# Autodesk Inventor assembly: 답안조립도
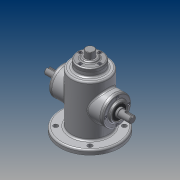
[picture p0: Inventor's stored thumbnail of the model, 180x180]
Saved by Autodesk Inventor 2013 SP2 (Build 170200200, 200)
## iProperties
Created: 2014-12
Part Number: 답안조립도
Document SubType Name: Assembly
Designer: user
Author: user
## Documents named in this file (12)
- C:\Users\user\Desktop\441228V1011\답안조립도.iam
- C:\Users\user\Desktop\441228V1011\본체.ipt
- C:\Users\user\Desktop\441228V1011\커버.ipt
- C:\Users\user\Desktop\441228V1011\상단커버.ipt
- C:\Users\user\Desktop\441228V1011\M3x0.5x8.ipt
- M3x0.5.ipt
- C:\Users\user\Desktop\441228V1011\오일실.ipt
- 오일실.ipt
- C:\Users\user\Desktop\441228V1011\베어링 6002.ipt
- 베어링 6002.ipt
- C:\Users\user\Desktop\441228V1011\편심축.ipt
- C:\Users\user\Desktop\441228V1011\슬라이드.ipt
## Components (12 placed, 1 different names)
1. M3x0.5:1 — 각도:2
2. M3x0.5:7
3. M3x0.5:8
4. M3x0.5:9
5. M3x0.5:3 — 각도:1
6. M3x0.5:10
7. M3x0.5:11
8. M3x0.5:12
9. M3x0.5:2 — 각도:3
10. M3x0.5:13
11. M3x0.5:14
12. M3x0.5:15
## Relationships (3: Angle 3)
- 각도:1 [Angle]: M3x0.5:3
- 각도:2 [Angle]: M3x0.5:1
- 각도:3 [Angle]: M3x0.5:2
